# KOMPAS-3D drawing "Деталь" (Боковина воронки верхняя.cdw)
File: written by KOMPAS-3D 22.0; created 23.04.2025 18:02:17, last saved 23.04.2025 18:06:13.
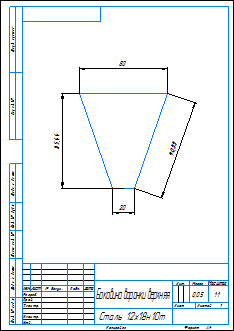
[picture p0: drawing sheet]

Sheet 1: A4, portrait

Document properties: Автор: Admin; Масса: 0.050341; Полное имя файла: Боковина верх 4шт.m3d

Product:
- Part/product: Деталь
    Масса: 0.050341

Title block, sheet 1: Наименование: Боковина воронки верхняя; Материал: Сталь 12х18н10т; Масса: 0,05; Количество листов документа: 1; Форматы листов документа: A4

Views: Вид 1, Спереди
Referenced files in D:\28.11.2016\3D модели\Абилимпикс\2025\Воронка квадратная\: Боковина верх 4шт.m3d
Dimensions and other numbers on the sheet: 80; 85,44; 20; 90,55; 1:1; 1; 0,05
